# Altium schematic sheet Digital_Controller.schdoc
size 594 x 419 mm; Symbol: Drawing-Symbol_A4; @Project Name: Inverted_MAML_6x6; @Page Count: 2; @Update Date: 2026-06-25; @Create Date: 2026-06-25; @Schematic Name: Inverted_MAML; @Page No: 0; @Page Name: P1; Company: EasyEDA.com; Version: V1.0; Page Size: A4; Device: Drawing-Symbol_A4; @Create Time: 17:43:39; @Update Time: 17:43:39; Border: 1; Width: 2338; Height: 1652; Region Start: 1; X Region Count: 6; Y Region Count: 4; Blade Width: 10; Title Block Position: 3; @Board Name: Analog_Matrix
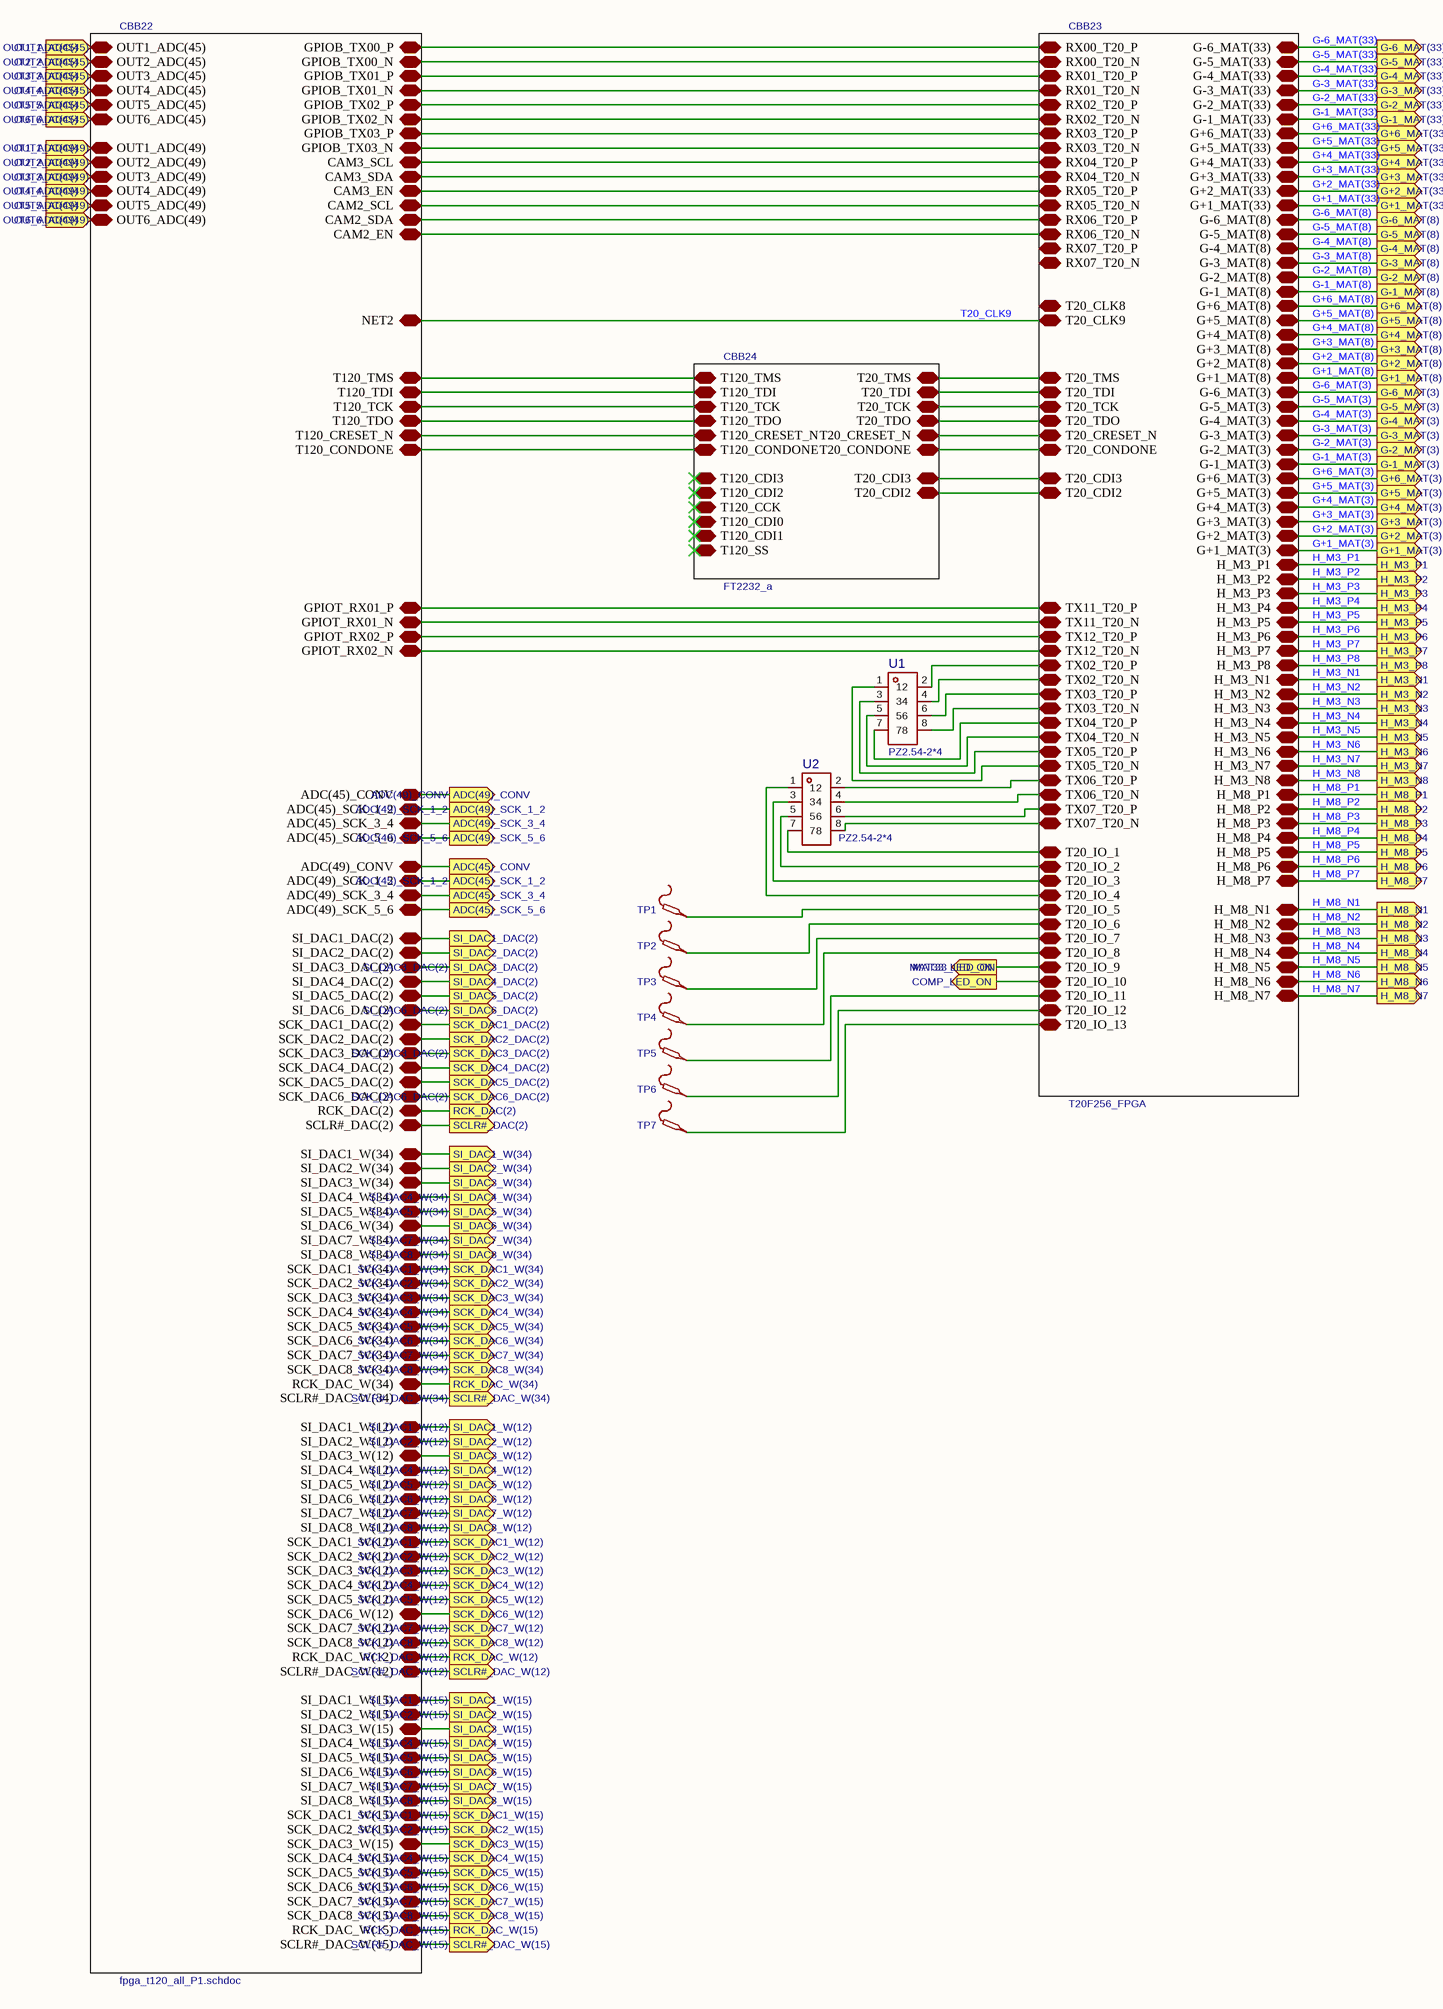
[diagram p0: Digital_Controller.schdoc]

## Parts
TP1  (no value)  [Test-Point-0.5mm]
TP2  (no value)  [Test-Point-0.5mm]
TP3  (no value)  [Test-Point-0.5mm]
TP4  (no value)  [Test-Point-0.5mm]
TP5  (no value)  [Test-Point-0.5mm]
TP6  (no value)  [Test-Point-0.5mm]
TP7  (no value)  [Test-Point-0.5mm]
U1  PZ2.54-2*4  [HDR-TH_8P-P2.54-V-M-R2-C4-S2.54]
U2  PZ2.54-2*4  [HDR-TH_8P-P2.54-V-M-R2-C4-S2.54]

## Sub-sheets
CBB22 = fpga_t120_all_P1.schdoc: T120_CRESET_N, NET2, T120_TCK, T120_TDI, T120_TMS, T120_TDO, T120_CONDONE, GPIOB_TX03_N, GPIOB_TX03_P, GPIOB_TX00_N, GPIOB_TX01_N, GPIOB_TX02_N, GPIOB_TX00_P, GPIOB_TX01_P, GPIOB_TX02_P, GPIOT_RX01_P, GPIOT_RX02_P, GPIOT_RX01_N, GPIOT_RX02_N, OUT1_ADC(45), OUT1_ADC(49), OUT2_ADC(45), OUT2_ADC(49), OUT3_ADC(45), OUT3_ADC(49), OUT4_ADC(45), OUT4_ADC(49), OUT5_ADC(45), OUT5_ADC(49), OUT6_ADC(45), OUT6_ADC(49), ADC(45)_SCK_5_6, ADC(49)_SCK_5_6, ADC(45)_SCK_3_4, ADC(49)_SCK_3_4, ADC(45)_SCK_1_2, ADC(49)_SCK_1_2, ADC(45)_CONV, ADC(49)_CONV, SCLR#_DAC(2), RCK_DAC(2), SCK_DAC6_DAC(2), SCK_DAC5_DAC(2), SCK_DAC4_DAC(2), SCK_DAC3_DAC(2), SCK_DAC2_DAC(2), SCK_DAC1_DAC(2), SI_DAC6_DAC(2), SI_DAC5_DAC(2), SI_DAC4_DAC(2), SI_DAC3_DAC(2), SI_DAC2_DAC(2), SI_DAC1_DAC(2), SCLR#_DAC_W(34), SCLR#_DAC_W(15), SCLR#_DAC_W(12), RCK_DAC_W(34), RCK_DAC_W(12), RCK_DAC_W(15), SCK_DAC8_W(34), SCK_DAC8_W(12), SCK_DAC8_W(15), SCK_DAC7_W(34), SCK_DAC7_W(12), SCK_DAC7_W(15), SCK_DAC6_W(34), SCK_DAC6_W(12), SCK_DAC6_W(15), SCK_DAC5_W(34), SCK_DAC5_W(12), SCK_DAC5_W(15), SCK_DAC4_W(34), SCK_DAC4_W(15), SCK_DAC4_W(12), SCK_DAC3_W(34), SCK_DAC3_W(15), SCK_DAC3_W(12), SCK_DAC2_W(15), SCK_DAC2_W(34), SCK_DAC2_W(12), SCK_DAC1_W(34), SCK_DAC1_W(12), SCK_DAC1_W(15), SI_DAC8_W(34), SI_DAC8_W(15), SI_DAC8_W(12), SI_DAC7_W(34), SI_DAC7_W(15), SI_DAC7_W(12), SI_DAC6_W(34), SI_DAC6_W(15), SI_DAC6_W(12), SI_DAC5_W(15), SI_DAC5_W(34), SI_DAC5_W(12), SI_DAC4_W(12), SI_DAC4_W(15), SI_DAC4_W(34), SI_DAC3_W(34), SI_DAC3_W(15), SI_DAC3_W(12), SI_DAC2_W(34), SI_DAC2_W(15), SI_DAC2_W(12), SI_DAC1_W(34), SI_DAC1_W(15), SI_DAC1_W(12), CAM2_EN, CAM2_SDA, CAM2_SCL, CAM3_EN, CAM3_SDA, CAM3_SCL  | Symbol: fpga_t120_all
CBB23 = P1.schdoc: G-6_MAT(33), G-5_MAT(33), G-4_MAT(33), G-3_MAT(33), G-2_MAT(33), G-1_MAT(33), G+6_MAT(33), G+5_MAT(33), G+4_MAT(33), G+3_MAT(33), G+2_MAT(33), G+1_MAT(33), G-6_MAT(8), G-5_MAT(8), G-4_MAT(8), G-3_MAT(8), G-2_MAT(8), G-1_MAT(8), G+6_MAT(8), G+5_MAT(8), G+4_MAT(8), G+3_MAT(8), G+2_MAT(8), G+1_MAT(8), G-6_MAT(3), G-5_MAT(3), G-4_MAT(3), G-3_MAT(3), G-2_MAT(3), G-1_MAT(3), G+6_MAT(3), G+5_MAT(3), G+4_MAT(3), G+3_MAT(3), G+2_MAT(3), G+1_MAT(3), H_M3_P1, H_M3_P2, H_M3_P3, H_M3_P4, H_M3_P5, H_M3_P6, H_M3_P7, H_M3_P8, H_M3_N1, H_M3_N2, H_M3_N3, H_M3_N4, H_M3_N5, H_M3_N6, H_M3_N7, H_M3_N8, H_M8_P1, H_M8_P2, H_M8_P3, H_M8_P4, H_M8_P5, H_M8_P6, H_M8_P7, H_M8_N1, H_M8_N2, H_M8_N3, H_M8_N4, H_M8_N5, H_M8_N6, H_M8_N7, RX00_T20_P, RX01_T20_P, RX02_T20_P, RX03_T20_P, RX04_T20_P, RX00_T20_N, RX01_T20_N, RX02_T20_N, RX03_T20_N, RX04_T20_N, RX05_T20_N, RX06_T20_N, RX07_T20_N, RX05_T20_P, RX06_T20_P, RX07_T20_P, TX11_T20_P, TX12_T20_P, TX02_T20_P, TX03_T20_P, TX04_T20_P, TX05_T20_P, TX06_T20_P, TX07_T20_P, TX11_T20_N, TX12_T20_N, TX02_T20_N, TX03_T20_N, TX04_T20_N, TX05_T20_N, TX06_T20_N, T20_CLK8, T20_CLK9, TX07_T20_N, T20_CRESET_N, T20_TDI, T20_TMS, T20_TCK, T20_TDO, T20_CONDONE, T20_CDI3, T20_CDI2, T20_IO_1, T20_IO_2, T20_IO_3, T20_IO_4, T20_IO_5, T20_IO_6, T20_IO_7, T20_IO_8, T20_IO_9, T20_IO_10, T20_IO_12, T20_IO_11, T20_IO_13  | Symbol: T20F256_FPGA
CBB24 = FT2232_a_P1.schdoc: T120_CRESET_N, T120_TDO, T120_CONDONE, T120_TCK, T120_TDI, T120_TMS, T120_CDI3, T120_CDI2, T120_CCK, T120_CDI0, T120_CDI1, T120_SS, T20_TDO, T20_CONDONE, T20_TCK, T20_TDI, T20_TMS, T20_CRESET_N, T20_CDI3, T20_CDI2  | Symbol: FT2232_a

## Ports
ADC(45)_CONV (out), ADC(45)_SCK_1_2 (out), ADC(45)_SCK_3_4 (out), ADC(45)_SCK_5_6 (out), ADC(49)_CONV (out), ADC(49)_SCK_1_2 (out), ADC(49)_SCK_3_4 (out), ADC(49)_SCK_5_6 (out), COMP_LED_ON (out), G+1_MAT(3) (out), G+1_MAT(8) (out), G+1_MAT(33) (out), G+2_MAT(3) (out), G+2_MAT(8) (out), G+2_MAT(33) (out), G+3_MAT(3) (out), G+3_MAT(8) (out), G+3_MAT(33) (out), G+4_MAT(3) (out), G+4_MAT(8) (out), G+4_MAT(33) (out), G+5_MAT(3) (out), G+5_MAT(8) (out), G+5_MAT(33) (out), G+6_MAT(3) (out), G+6_MAT(8) (out), G+6_MAT(33) (out), G-1_MAT(3) (out), G-1_MAT(8) (out), G-1_MAT(33) (out), G-2_MAT(3) (out), G-2_MAT(8) (out), G-2_MAT(33) (out), G-3_MAT(3) (out), G-3_MAT(8) (out), G-3_MAT(33) (out), G-4_MAT(3) (out), G-4_MAT(8) (out), G-4_MAT(33) (out), G-5_MAT(3) (out), G-5_MAT(8) (out), G-5_MAT(33) (out), G-6_MAT(3) (out), G-6_MAT(8) (out), G-6_MAT(33) (out), H_M3_N1 (out), H_M3_N2 (out), H_M3_N3 (out), H_M3_N4 (out), H_M3_N5 (out), H_M3_N6 (out), H_M3_N7 (out), H_M3_N8 (out), H_M3_P1 (out), H_M3_P2 (out), H_M3_P3 (out), H_M3_P4 (out), H_M3_P5 (out), H_M3_P6 (out), H_M3_P7 (out), H_M3_P8 (out), H_M8_N1 (out), H_M8_N2 (out), H_M8_N3 (out), H_M8_N4 (out), H_M8_N5 (out), H_M8_N6 (out), H_M8_N7 (out), H_M8_P1 (out), H_M8_P2 (out), H_M8_P3 (out), H_M8_P4 (out), H_M8_P5 (out), H_M8_P6 (out), H_M8_P7 (out), MAT33_LED_ON (out), OUT1_ADC(45) (in), OUT1_ADC(49) (in), OUT2_ADC(45) (in), OUT2_ADC(49) (in), OUT3_ADC(45) (in), OUT3_ADC(49) (in), OUT4_ADC(45) (in), OUT4_ADC(49) (in), OUT5_ADC(45) (in), OUT5_ADC(49) (in), OUT6_ADC(45) (in), OUT6_ADC(49) (in), RCK_DAC(2) (out), RCK_DAC_W(12) (out), RCK_DAC_W(15) (out), RCK_DAC_W(34) (out), SCK_DAC1_DAC(2) (out), SCK_DAC1_W(12) (out), SCK_DAC1_W(15) (out), SCK_DAC1_W(34) (out), SCK_DAC2_DAC(2) (out), SCK_DAC2_W(12) (out), SCK_DAC2_W(15) (out), SCK_DAC2_W(34) (out), SCK_DAC3_DAC(2) (out), SCK_DAC3_W(12) (out), SCK_DAC3_W(15) (out), SCK_DAC3_W(34) (out), SCK_DAC4_DAC(2) (out), SCK_DAC4_W(12) (out), SCK_DAC4_W(15) (out), SCK_DAC4_W(34) (out), SCK_DAC5_DAC(2) (out), SCK_DAC5_W(12) (out), SCK_DAC5_W(15) (out), SCK_DAC5_W(34) (out), SCK_DAC6_DAC(2) (out), SCK_DAC6_W(12) (out), SCK_DAC6_W(15) (out), SCK_DAC6_W(34) (out), SCK_DAC7_W(12) (out), SCK_DAC7_W(15) (out), SCK_DAC7_W(34) (out), SCK_DAC8_W(12) (out), SCK_DAC8_W(15) (out), SCK_DAC8_W(34) (out), SCLR#_DAC(2) (out), SCLR#_DAC_W(12) (out), SCLR#_DAC_W(15) (out), SCLR#_DAC_W(34) (out), SI_DAC1_DAC(2) (out), SI_DAC1_W(12) (out), SI_DAC1_W(15) (out), SI_DAC1_W(34) (out), SI_DAC2_DAC(2) (out), SI_DAC2_W(12) (out), SI_DAC2_W(15) (out), SI_DAC2_W(34) (out), SI_DAC3_DAC(2) (out), SI_DAC3_W(12) (out), SI_DAC3_W(15) (out), SI_DAC3_W(34) (out), SI_DAC4_DAC(2) (out), SI_DAC4_W(12) (out), SI_DAC4_W(15) (out), SI_DAC4_W(34) (out), SI_DAC5_DAC(2) (out), SI_DAC5_W(12) (out), SI_DAC5_W(15) (out), SI_DAC5_W(34) (out), SI_DAC6_DAC(2) (out), SI_DAC6_W(12) (out), SI_DAC6_W(15) (out), SI_DAC6_W(34) (out), SI_DAC7_W(12) (out), SI_DAC7_W(15) (out), SI_DAC7_W(34) (out), SI_DAC8_W(12) (out), SI_DAC8_W(15) (out), SI_DAC8_W(34) (out)

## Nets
ADC(45)_CONV: port ADC(45)_CONV, sheet CBB22/ADC(49)_CONV
ADC(45)_SCK_1_2: port ADC(45)_SCK_1_2, sheet CBB22/ADC(49)_SCK_1_2
ADC(45)_SCK_3_4: port ADC(45)_SCK_3_4, sheet CBB22/ADC(49)_SCK_3_4
ADC(45)_SCK_5_6: port ADC(45)_SCK_5_6, sheet CBB22/ADC(49)_SCK_5_6
ADC(49)_CONV: port ADC(49)_CONV, sheet CBB22/ADC(45)_CONV
ADC(49)_SCK_1_2: port ADC(49)_SCK_1_2, sheet CBB22/ADC(45)_SCK_1_2
ADC(49)_SCK_3_4: port ADC(49)_SCK_3_4, sheet CBB22/ADC(45)_SCK_3_4
ADC(49)_SCK_5_6: port ADC(49)_SCK_5_6, sheet CBB22/ADC(45)_SCK_5_6
COMP_LED_ON: port COMP_LED_ON, sheet CBB23/T20_IO_10
G+1_MAT(3): port G+1_MAT(3), sheet CBB23/G+1_MAT(3)
G+1_MAT(8): port G+1_MAT(8), sheet CBB23/G+1_MAT(8)
G+1_MAT(33): port G+1_MAT(33), sheet CBB23/G+1_MAT(33)
G+2_MAT(3): port G+2_MAT(3), sheet CBB23/G+2_MAT(3)
G+2_MAT(8): port G+2_MAT(8), sheet CBB23/G+2_MAT(8)
G+2_MAT(33): port G+2_MAT(33), sheet CBB23/G+2_MAT(33)
G+3_MAT(3): port G+3_MAT(3), sheet CBB23/G+3_MAT(3)
G+3_MAT(8): port G+3_MAT(8), sheet CBB23/G+3_MAT(8)
G+3_MAT(33): port G+3_MAT(33), sheet CBB23/G+3_MAT(33)
G+4_MAT(3): port G+4_MAT(3), sheet CBB23/G+4_MAT(3)
G+4_MAT(8): port G+4_MAT(8), sheet CBB23/G+4_MAT(8)
G+4_MAT(33): port G+4_MAT(33), sheet CBB23/G+4_MAT(33)
G+5_MAT(3): port G+5_MAT(3), sheet CBB23/G+5_MAT(3)
G+5_MAT(8): port G+5_MAT(8), sheet CBB23/G+5_MAT(8)
G+5_MAT(33): port G+5_MAT(33), sheet CBB23/G+5_MAT(33)
G+6_MAT(3): port G+6_MAT(3), sheet CBB23/G+6_MAT(3)
G+6_MAT(8): port G+6_MAT(8), sheet CBB23/G+6_MAT(8)
G+6_MAT(33): port G+6_MAT(33), sheet CBB23/G+6_MAT(33)
G-1_MAT(3): port G-1_MAT(3), sheet CBB23/G-1_MAT(3)
G-1_MAT(8): port G-1_MAT(8), sheet CBB23/G-1_MAT(8)
G-1_MAT(33): port G-1_MAT(33), sheet CBB23/G-1_MAT(33)
G-2_MAT(3): port G-2_MAT(3), sheet CBB23/G-2_MAT(3)
G-2_MAT(8): port G-2_MAT(8), sheet CBB23/G-2_MAT(8)
G-2_MAT(33): port G-2_MAT(33), sheet CBB23/G-2_MAT(33)
G-3_MAT(3): port G-3_MAT(3), sheet CBB23/G-3_MAT(3)
G-3_MAT(8): port G-3_MAT(8), sheet CBB23/G-3_MAT(8)
G-3_MAT(33): port G-3_MAT(33), sheet CBB23/G-3_MAT(33)
G-4_MAT(3): port G-4_MAT(3), sheet CBB23/G-4_MAT(3)
G-4_MAT(8): port G-4_MAT(8), sheet CBB23/G-4_MAT(8)
G-4_MAT(33): port G-4_MAT(33), sheet CBB23/G-4_MAT(33)
G-5_MAT(3): port G-5_MAT(3), sheet CBB23/G-5_MAT(3)
G-5_MAT(8): port G-5_MAT(8), sheet CBB23/G-5_MAT(8)
G-5_MAT(33): port G-5_MAT(33), sheet CBB23/G-5_MAT(33)
G-6_MAT(3): port G-6_MAT(3), sheet CBB23/G-6_MAT(3)
G-6_MAT(8): port G-6_MAT(8), sheet CBB23/G-6_MAT(8)
G-6_MAT(33): port G-6_MAT(33), sheet CBB23/G-6_MAT(33)
H_M3_N1: port H_M3_N1, sheet CBB23/H_M3_N1
H_M3_N2: port H_M3_N2, sheet CBB23/H_M3_N2
H_M3_N3: port H_M3_N3, sheet CBB23/H_M3_N3
H_M3_N4: port H_M3_N4, sheet CBB23/H_M3_N4
H_M3_N5: port H_M3_N5, sheet CBB23/H_M3_N5
H_M3_N6: port H_M3_N6, sheet CBB23/H_M3_N6
H_M3_N7: port H_M3_N7, sheet CBB23/H_M3_N7
H_M3_N8: port H_M3_N8, sheet CBB23/H_M3_N8
H_M3_P1: port H_M3_P1, sheet CBB23/H_M3_P1
H_M3_P2: port H_M3_P2, sheet CBB23/H_M3_P2
H_M3_P3: port H_M3_P3, sheet CBB23/H_M3_P3
H_M3_P4: port H_M3_P4, sheet CBB23/H_M3_P4
H_M3_P5: port H_M3_P5, sheet CBB23/H_M3_P5
H_M3_P6: port H_M3_P6, sheet CBB23/H_M3_P6
H_M3_P7: port H_M3_P7, sheet CBB23/H_M3_P7
H_M3_P8: port H_M3_P8, sheet CBB23/H_M3_P8
H_M8_N1: port H_M8_N1, sheet CBB23/H_M8_N1
H_M8_N2: port H_M8_N2, sheet CBB23/H_M8_N2
H_M8_N3: port H_M8_N3, sheet CBB23/H_M8_N3
H_M8_N4: port H_M8_N4, sheet CBB23/H_M8_N4
H_M8_N5: port H_M8_N5, sheet CBB23/H_M8_N5
H_M8_N6: port H_M8_N6, sheet CBB23/H_M8_N6
H_M8_N7: port H_M8_N7, sheet CBB23/H_M8_N7
H_M8_P1: port H_M8_P1, sheet CBB23/H_M8_P1
H_M8_P2: port H_M8_P2, sheet CBB23/H_M8_P2
H_M8_P3: port H_M8_P3, sheet CBB23/H_M8_P3
H_M8_P4: port H_M8_P4, sheet CBB23/H_M8_P4
H_M8_P5: port H_M8_P5, sheet CBB23/H_M8_P5
H_M8_P6: port H_M8_P6, sheet CBB23/H_M8_P6
H_M8_P7: port H_M8_P7, sheet CBB23/H_M8_P7
MAT33_LED_ON: port MAT33_LED_ON, sheet CBB23/T20_IO_9
OUT1_ADC(45): port OUT1_ADC(45), sheet CBB22/OUT1_ADC(45)
OUT1_ADC(49): port OUT1_ADC(49), sheet CBB22/OUT1_ADC(49)
OUT2_ADC(45): port OUT2_ADC(45), sheet CBB22/OUT2_ADC(45)
OUT2_ADC(49): port OUT2_ADC(49), sheet CBB22/OUT2_ADC(49)
OUT3_ADC(45): port OUT3_ADC(45), sheet CBB22/OUT3_ADC(45)
OUT3_ADC(49): port OUT3_ADC(49), sheet CBB22/OUT3_ADC(49)
OUT4_ADC(45): port OUT4_ADC(45), sheet CBB22/OUT4_ADC(45)
OUT4_ADC(49): port OUT4_ADC(49), sheet CBB22/OUT4_ADC(49)
OUT5_ADC(45): port OUT5_ADC(45), sheet CBB22/OUT5_ADC(45)
OUT5_ADC(49): port OUT5_ADC(49), sheet CBB22/OUT5_ADC(49)
OUT6_ADC(45): port OUT6_ADC(45), sheet CBB22/OUT6_ADC(45)
OUT6_ADC(49): port OUT6_ADC(49), sheet CBB22/OUT6_ADC(49)
RCK_DAC(2): port RCK_DAC(2), sheet CBB22/RCK_DAC(2)
RCK_DAC_W(12): port RCK_DAC_W(12), sheet CBB22/RCK_DAC_W(12)
RCK_DAC_W(15): port RCK_DAC_W(15), sheet CBB22/RCK_DAC_W(15)
RCK_DAC_W(34): port RCK_DAC_W(34), sheet CBB22/RCK_DAC_W(34)
SCK_DAC1_DAC(2): port SCK_DAC1_DAC(2), sheet CBB22/SCK_DAC1_DAC(2)
SCK_DAC1_W(12): port SCK_DAC1_W(12), sheet CBB22/SCK_DAC1_W(12)
SCK_DAC1_W(15): port SCK_DAC1_W(15), sheet CBB22/SCK_DAC1_W(15)
SCK_DAC1_W(34): port SCK_DAC1_W(34), sheet CBB22/SCK_DAC1_W(34)
SCK_DAC2_DAC(2): port SCK_DAC2_DAC(2), sheet CBB22/SCK_DAC2_DAC(2)
SCK_DAC2_W(12): port SCK_DAC2_W(12), sheet CBB22/SCK_DAC2_W(12)
SCK_DAC2_W(15): port SCK_DAC2_W(15), sheet CBB22/SCK_DAC2_W(15)
SCK_DAC2_W(34): port SCK_DAC2_W(34), sheet CBB22/SCK_DAC2_W(34)
SCK_DAC3_DAC(2): port SCK_DAC3_DAC(2), sheet CBB22/SCK_DAC3_DAC(2)
SCK_DAC3_W(12): port SCK_DAC3_W(12), sheet CBB22/SCK_DAC3_W(12)
SCK_DAC3_W(15): port SCK_DAC3_W(15), sheet CBB22/SCK_DAC3_W(15)
SCK_DAC3_W(34): port SCK_DAC3_W(34), sheet CBB22/SCK_DAC3_W(34)
SCK_DAC4_DAC(2): port SCK_DAC4_DAC(2), sheet CBB22/SCK_DAC4_DAC(2)
SCK_DAC4_W(12): port SCK_DAC4_W(12), sheet CBB22/SCK_DAC4_W(12)
SCK_DAC4_W(15): port SCK_DAC4_W(15), sheet CBB22/SCK_DAC4_W(15)
SCK_DAC4_W(34): port SCK_DAC4_W(34), sheet CBB22/SCK_DAC4_W(34)
SCK_DAC5_DAC(2): port SCK_DAC5_DAC(2), sheet CBB22/SCK_DAC5_DAC(2)
SCK_DAC5_W(12): port SCK_DAC5_W(12), sheet CBB22/SCK_DAC5_W(12)
SCK_DAC5_W(15): port SCK_DAC5_W(15), sheet CBB22/SCK_DAC5_W(15)
SCK_DAC5_W(34): port SCK_DAC5_W(34), sheet CBB22/SCK_DAC5_W(34)
SCK_DAC6_DAC(2): port SCK_DAC6_DAC(2), sheet CBB22/SCK_DAC6_DAC(2)
SCK_DAC6_W(12): port SCK_DAC6_W(12), sheet CBB22/SCK_DAC6_W(12)
SCK_DAC6_W(15): port SCK_DAC6_W(15), sheet CBB22/SCK_DAC6_W(15)
SCK_DAC6_W(34): port SCK_DAC6_W(34), sheet CBB22/SCK_DAC6_W(34)
SCK_DAC7_W(12): port SCK_DAC7_W(12), sheet CBB22/SCK_DAC7_W(12)
SCK_DAC7_W(15): port SCK_DAC7_W(15), sheet CBB22/SCK_DAC7_W(15)
SCK_DAC7_W(34): port SCK_DAC7_W(34), sheet CBB22/SCK_DAC7_W(34)
SCK_DAC8_W(12): port SCK_DAC8_W(12), sheet CBB22/SCK_DAC8_W(12)
SCK_DAC8_W(15): port SCK_DAC8_W(15), sheet CBB22/SCK_DAC8_W(15)
SCK_DAC8_W(34): port SCK_DAC8_W(34), sheet CBB22/SCK_DAC8_W(34)
SCLR#_DAC(2): port SCLR#_DAC(2), sheet CBB22/SCLR#_DAC(2)
SCLR#_DAC_W(12): port SCLR#_DAC_W(12), sheet CBB22/SCLR#_DAC_W(12)
SCLR#_DAC_W(15): port SCLR#_DAC_W(15), sheet CBB22/SCLR#_DAC_W(15)
SCLR#_DAC_W(34): port SCLR#_DAC_W(34), sheet CBB22/SCLR#_DAC_W(34)
SI_DAC1_DAC(2): port SI_DAC1_DAC(2), sheet CBB22/SI_DAC1_DAC(2)
SI_DAC1_W(12): port SI_DAC1_W(12), sheet CBB22/SI_DAC1_W(12)
SI_DAC1_W(15): port SI_DAC1_W(15), sheet CBB22/SI_DAC1_W(15)
SI_DAC1_W(34): port SI_DAC1_W(34), sheet CBB22/SI_DAC1_W(34)
SI_DAC2_DAC(2): port SI_DAC2_DAC(2), sheet CBB22/SI_DAC2_DAC(2)
SI_DAC2_W(12): port SI_DAC2_W(12), sheet CBB22/SI_DAC2_W(12)
SI_DAC2_W(15): port SI_DAC2_W(15), sheet CBB22/SI_DAC2_W(15)
SI_DAC2_W(34): port SI_DAC2_W(34), sheet CBB22/SI_DAC2_W(34)
SI_DAC3_DAC(2): port SI_DAC3_DAC(2), sheet CBB22/SI_DAC3_DAC(2)
SI_DAC3_W(12): port SI_DAC3_W(12), sheet CBB22/SI_DAC3_W(12)
SI_DAC3_W(15): port SI_DAC3_W(15), sheet CBB22/SI_DAC3_W(15)
SI_DAC3_W(34): port SI_DAC3_W(34), sheet CBB22/SI_DAC3_W(34)
SI_DAC4_DAC(2): port SI_DAC4_DAC(2), sheet CBB22/SI_DAC4_DAC(2)
SI_DAC4_W(12): port SI_DAC4_W(12), sheet CBB22/SI_DAC4_W(12)
SI_DAC4_W(15): port SI_DAC4_W(15), sheet CBB22/SI_DAC4_W(15)
SI_DAC4_W(34): port SI_DAC4_W(34), sheet CBB22/SI_DAC4_W(34)
SI_DAC5_DAC(2): port SI_DAC5_DAC(2), sheet CBB22/SI_DAC5_DAC(2)
SI_DAC5_W(12): port SI_DAC5_W(12), sheet CBB22/SI_DAC5_W(12)
SI_DAC5_W(15): port SI_DAC5_W(15), sheet CBB22/SI_DAC5_W(15)
SI_DAC5_W(34): port SI_DAC5_W(34), sheet CBB22/SI_DAC5_W(34)
SI_DAC6_DAC(2): port SI_DAC6_DAC(2), sheet CBB22/SI_DAC6_DAC(2)
SI_DAC6_W(12): port SI_DAC6_W(12), sheet CBB22/SI_DAC6_W(12)
SI_DAC6_W(15): port SI_DAC6_W(15), sheet CBB22/SI_DAC6_W(15)
SI_DAC6_W(34): port SI_DAC6_W(34), sheet CBB22/SI_DAC6_W(34)
SI_DAC7_W(12): port SI_DAC7_W(12), sheet CBB22/SI_DAC7_W(12)
SI_DAC7_W(15): port SI_DAC7_W(15), sheet CBB22/SI_DAC7_W(15)
SI_DAC7_W(34): port SI_DAC7_W(34), sheet CBB22/SI_DAC7_W(34)
SI_DAC8_W(12): port SI_DAC8_W(12), sheet CBB22/SI_DAC8_W(12)
SI_DAC8_W(15): port SI_DAC8_W(15), sheet CBB22/SI_DAC8_W(15)
SI_DAC8_W(34): port SI_DAC8_W(34), sheet CBB22/SI_DAC8_W(34)
T20_CLK9: sheet CBB22/NET2, sheet CBB23/T20_CLK9
NetTP1_1: TP1.1 ; sheet CBB23/T20_IO_5
NetTP2_1: TP2.1 ; sheet CBB23/T20_IO_6
NetTP3_1: TP3.1 ; sheet CBB23/T20_IO_7
NetTP4_1: TP4.1 ; sheet CBB23/T20_IO_8
NetTP5_1: TP5.1 ; sheet CBB23/T20_IO_11
NetTP6_1: TP6.1 ; sheet CBB23/T20_IO_12
NetTP7_1: TP7.1 ; sheet CBB23/T20_IO_13
NetU1_1: U1.1 ; sheet CBB23/TX05_T20_N
NetU1_2: U1.2 ; sheet CBB23/TX02_T20_P
NetU1_3: U1.3 ; sheet CBB23/TX05_T20_P
NetU1_4: U1.4 ; sheet CBB23/TX02_T20_N
NetU1_5: U1.5 ; sheet CBB23/TX04_T20_N
NetU1_6: U1.6 ; sheet CBB23/TX03_T20_P
NetU1_7: U1.7 ; sheet CBB23/TX04_T20_P
NetU1_8: U1.8 ; sheet CBB23/TX03_T20_N
NetU2_1: U2.1 ; sheet CBB23/T20_IO_4
NetU2_2: U2.2 ; sheet CBB23/TX06_T20_P
NetU2_3: U2.3 ; sheet CBB23/T20_IO_3
NetU2_4: U2.4 ; sheet CBB23/TX06_T20_N
NetU2_5: U2.5 ; sheet CBB23/T20_IO_2
NetU2_6: U2.6 ; sheet CBB23/TX07_T20_P
NetU2_7: U2.7 ; sheet CBB23/T20_IO_1
NetU2_8: U2.8 ; sheet CBB23/TX07_T20_N
(unnamed): sheet CBB22/T120_CRESET_N, sheet CBB24/T120_CRESET_N
(unnamed): sheet CBB22/T120_TCK, sheet CBB24/T120_TCK  [a separate net that carries the same name]
(unnamed): sheet CBB22/T120_TDI, sheet CBB24/T120_TDI  [a separate net that carries the same name]
(unnamed): sheet CBB22/T120_TMS, sheet CBB24/T120_TMS  [a separate net that carries the same name]
(unnamed): sheet CBB22/T120_TDO, sheet CBB24/T120_TDO  [a separate net that carries the same name]
(unnamed): sheet CBB22/T120_CONDONE, sheet CBB24/T120_CONDONE  [a separate net that carries the same name]
(unnamed): sheet CBB22/GPIOB_TX03_N, sheet CBB23/RX03_T20_N  [a separate net that carries the same name]
(unnamed): sheet CBB22/GPIOB_TX03_P, sheet CBB23/RX03_T20_P  [a separate net that carries the same name]
(unnamed): sheet CBB22/GPIOB_TX00_N, sheet CBB23/RX00_T20_N  [a separate net that carries the same name]
(unnamed): sheet CBB22/GPIOB_TX01_N, sheet CBB23/RX01_T20_N  [a separate net that carries the same name]
(unnamed): sheet CBB22/GPIOB_TX02_N, sheet CBB23/RX02_T20_N  [a separate net that carries the same name]
(unnamed): sheet CBB22/GPIOB_TX00_P, sheet CBB23/RX00_T20_P  [a separate net that carries the same name]
(unnamed): sheet CBB22/GPIOB_TX01_P, sheet CBB23/RX01_T20_P  [a separate net that carries the same name]
(unnamed): sheet CBB22/GPIOB_TX02_P, sheet CBB23/RX02_T20_P  [a separate net that carries the same name]
(unnamed): sheet CBB22/GPIOT_RX01_P, sheet CBB23/TX11_T20_P  [a separate net that carries the same name]
(unnamed): sheet CBB22/GPIOT_RX02_P, sheet CBB23/TX12_T20_P  [a separate net that carries the same name]
(unnamed): sheet CBB22/GPIOT_RX01_N, sheet CBB23/TX11_T20_N  [a separate net that carries the same name]
(unnamed): sheet CBB22/GPIOT_RX02_N, sheet CBB23/TX12_T20_N  [a separate net that carries the same name]
(unnamed): sheet CBB22/CAM2_EN, sheet CBB23/RX06_T20_N  [a separate net that carries the same name]
(unnamed): sheet CBB22/CAM2_SDA, sheet CBB23/RX06_T20_P  [a separate net that carries the same name]
(unnamed): sheet CBB22/CAM2_SCL, sheet CBB23/RX05_T20_N  [a separate net that carries the same name]
(unnamed): sheet CBB22/CAM3_EN, sheet CBB23/RX05_T20_P  [a separate net that carries the same name]
(unnamed): sheet CBB22/CAM3_SDA, sheet CBB23/RX04_T20_N  [a separate net that carries the same name]
(unnamed): sheet CBB22/CAM3_SCL, sheet CBB23/RX04_T20_P  [a separate net that carries the same name]
(unnamed): sheet CBB23/T20_CRESET_N, sheet CBB24/T20_CRESET_N  [a separate net that carries the same name]
(unnamed): sheet CBB23/T20_TDI, sheet CBB24/T20_TDI  [a separate net that carries the same name]
(unnamed): sheet CBB23/T20_TMS, sheet CBB24/T20_TMS  [a separate net that carries the same name]
(unnamed): sheet CBB23/T20_TCK, sheet CBB24/T20_TCK  [a separate net that carries the same name]
(unnamed): sheet CBB23/T20_TDO, sheet CBB24/T20_TDO  [a separate net that carries the same name]
(unnamed): sheet CBB23/T20_CONDONE, sheet CBB24/T20_CONDONE  [a separate net that carries the same name]
(unnamed): sheet CBB23/T20_CDI3, sheet CBB24/T20_CDI3  [a separate net that carries the same name]
(unnamed): sheet CBB23/T20_CDI2, sheet CBB24/T20_CDI2  [a separate net that carries the same name]

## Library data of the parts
TP1-TP7 = Test-Point: Test Point 测试点; AddInBom: yes
U1 U2 = PZ2.54-2*4: Pin Structure:2x4P Pitch:2.54mm Number of Rows:双排 Number of Pins:8P; Manufacturer: ZHOURI(洲日); Check: true; 3D Model: 47b5ce995b664298ab05f1b74b77106f; 3D Model Transform: 399.999,200,0,0,0,0,0,0,-118.11; Pin Structure: 2x4P; Pitch: 2.54mm; AddInBom: yes; ModelName: HDR-TH_8P-P2.54-M-LI-2X4P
